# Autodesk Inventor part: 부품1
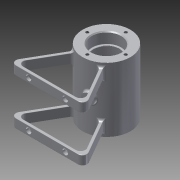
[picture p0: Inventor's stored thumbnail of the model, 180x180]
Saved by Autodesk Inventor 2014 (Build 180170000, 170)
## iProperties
Created: 2016-03
Part Number: 부품1
Material: 알루미늄 6061
Document SubType Name: Modeling
Designer: 406-017
Density: 2.71 g/cm^3
Appearance: 알루미늄 - 평지
Mass: 212.639 g
Surface Area: 335.819 cm^2
Volume: 78.4645 cm^3
Author: 406-017
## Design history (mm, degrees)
sketch "스케치1"
  geometry: C1 r 26 at (0, 0); 1 further point
  constraints: 1 centre point, 1 coincident
  dimensions: "d0" = 52 diameter of C1
extrude "돌출1" new body sketch "스케치1" distance "d1" = 70; taper "d2" = 0 deg
sketch "스케치2"
  geometry: L1 (16, 0)-(16, -12); L2 (16, -12)-(14, -12); L3 (14, -12)-(14, -14); L4 (14, -14)-(21, -14); L5 (21, -14)-(21, -56); L6 (21, -56)-(14, -56); L7 (14, -56)-(14, -58); L8 (14, -58)-(16, -58); L9 (16, -58)-(16, -70); L10 (16, -70)-(0, -70); L11 (0, -70)-(0, 0); L12 (0, 0)-(16, 0)
  constraints: 24 end point, 9 parallel, 1 collinear, 1 perpendicular, 1 vertical
  dimensions: "d3" = 32 diameter of L1 L11; "d4" = 42 diameter of L5 L11; "d5" = 32 diameter of L9 L11; "d6" = 2 distance of L2.end L3.end; "d7" = 2 distance of L6.end L7.end; "d8" = 12 distance of L8.end L9.end; "d9" = 42 distance of L4.end L5.end; "d10" = 12 distance of L1.start L1.end; "d11" = 28 diameter of L3 L11; "d12" = 28 diameter of L7 L11
node "작업 평면1"
sketch "스케치3"
  geometry: L1 (-26, -70)-(26, -70) reference; C1 r 5 at (0, -35); 1 further point
  constraints: 1 centre point, 1 vertical alignment
  dimensions: "d15" = 10 diameter of C1; "d16" = 35 distance from line of L1 C1.centre
extrude "돌출2" join sketch "스케치3" distance "d17" = 5; taper "d18" = 0 deg
node "작업 평면2"
sketch "스케치4"
  geometry: L1 (0, 0)-(0, -26.03); L2 (0, 0)-(7.506, -28.012)
  constraints: 4 end point, 1 vertical
  dimensions: "d20" = 15 deg angle of L1 L2; "d21" = 29 distance of L1.start L2.end; "d22" = 26.02996 distance of L1.start L1.end
node "작업 평면3"
sketch "스케치5"
  geometry: C1 r 6 at (0, 0); 1 further point
  constraints: 1 centre point, 1 vertical alignment
  dimensions: "d23" = 12 diameter of C1; "d24" = 35 distance of point (0, 35) C1.centre
extrude "돌출3" join sketch "스케치5" distance "d25" = 5; taper "d26" = 0 deg
node "작업 평면4"
sketch "스케치6"
  geometry: L1 (-16.613, -20)-(-42.594, -65); L2 (-42.594, -65)-(42.594, -65); L3 (42.594, -65)-(16.613, -20); L4 (16.613, -20)-(-16.613, -20); L5 (0, 0)-(0, -65); L6 (13.677, -20.913)-(37.398, -62); L7 (37.398, -62)-(-37.398, -62); L8 (-37.398, -62)-(-13.677, -20.913); L9 (-13.677, -20.913)-(13.677, -20.913); 2 further points
  constraints: 18 end point, 2 midpoint, 2 parallel, 1 horizontal, 1 perpendicular, 1 point on line, 2 other
  dimensions: "d28" = 30 deg angle of L5 L1; "d29" = 30 deg angle of L5 L3; "d32" = 65 distance from line of L2 L5.start; "d33" = 45 distance from line of L2 L3.end; "d34" = 3 distance between parallel lines of L2 L7; "d35" = 3 distance between parallel lines of L1 L8; "d36" = 3 distance between parallel lines of L6 L3; "d37" = 0.91346 distance between parallel lines of L4 L9
extrude "돌출4" join sketch "스케치6" distance "d38" = 10; taper "d39" = 0 deg
node "작업 평면5"
sketch "스케치7"
  geometry: C1 r 5 at (0, 0) reference; 2 further points
  constraints: 1 coincident
hole "구멍1" sketch "스케치7" at (0, 0) diameter "d41" = 5.188; stored, may be unused: countersink angle "d45" = 90 deg, drill point angle "d47" = 118 deg; dims "d42" = 10, "d43" = 4, "d44" = 2, "d46" = 11
revolve "회전2" stored, may be unused: angle "d48" = 90 deg
sketch "스케치10"
  geometry: L1 (0, 0)-(0, 21); C1 r 16 at (0, 0) reference; C2 r 26 at (0, 0) reference
  constraints: 2 end point, 1 vertical
  dimensions: "d49" = 21 distance of L1.end C1.centre
hole "구멍2" sketch "스케치10" at (0, 21) diameter "d50" = 3.242; stored, may be unused: countersink angle "d54" = 90 deg, drill point angle "d56" = 118 deg; dims "d51" = 8, "d52" = 4, "d53" = 2, "d55" = 10
sketch "스케치11"
  geometry: L1 (0, 10)-(74.796, 10) reference; C1 r 3 at (17.398, 5); C2 r 3 at (57.398, 5); 1 further point
  constraints: 2 centre point
  dimensions: "d60" = 6 diameter of C1; "d61" = 6 diameter of C2; "d62" = 5 distance from line of L1 C2.centre; "d63" = 20 horizontal distance of point (37.398, -5) C2.centre; "d64" = 40 distance of C2.centre C1.centre; "d65" = 20 horizontal distance of C1.centre point (37.398, -5)
extrude "돌출5" cut sketch "스케치11" distance "d66" = 20; taper "d67" = 0 deg
sketch "스케치12"
  geometry: C1 r 6 at (0, 0) reference; 2 further points
  constraints: 1 coincident
hole "구멍3" sketch "스케치12" at (0, 0) diameter "d68" = 5.188; stored, may be unused: countersink angle "d72" = 90 deg, drill point angle "d74" = 118 deg; dims "d69" = 8, "d70" = 4, "d71" = 2, "d73" = 10
fillet "모깎기2" dims "d76" = 0.3
fillet "모깎기3" dims "d77" = 3
node "작업 평면7"
  node "작업 평면6"
sketch "스케치15"
  geometry: L1 (-26, -70)-(26, -70) reference; 2 further points
  constraints: 1 vertical alignment, 1 other
  dimensions: "d79" = 35 distance from line of L1 point (0, -35)
feature "엠보싱1" sketch "스케치15" dims "d0" = 52, "d80" = 0.5, "d81" = 0
chamfer "모따기1" distance "d82" = 1; stored, may be unused: second distance "d83" = 2, angle "d84" = 45 deg
fillet "모깎기4" dims "d85" = 2
fillet "모깎기5" dims "d86" = 3
fillet "모깎기6" dims "d87" = 5
fillet "모깎기8" dims "d89" = 5
fillet "모깎기9" dims "d90" = 3
fillet "모깎기10" dims "d91" = 3
fillet "모깎기11" dims "d92" = 0.5
node "솔리드1"
mirror "대칭1"
pattern_circular "원형 패턴1" dims angle "d58" = 360 deg
mirror "대칭2"
mirror "대칭3"
other parameters: "d14" = 29, "d19" = -35, "d27" = -5, "d40" = -35, "d78" = -52
